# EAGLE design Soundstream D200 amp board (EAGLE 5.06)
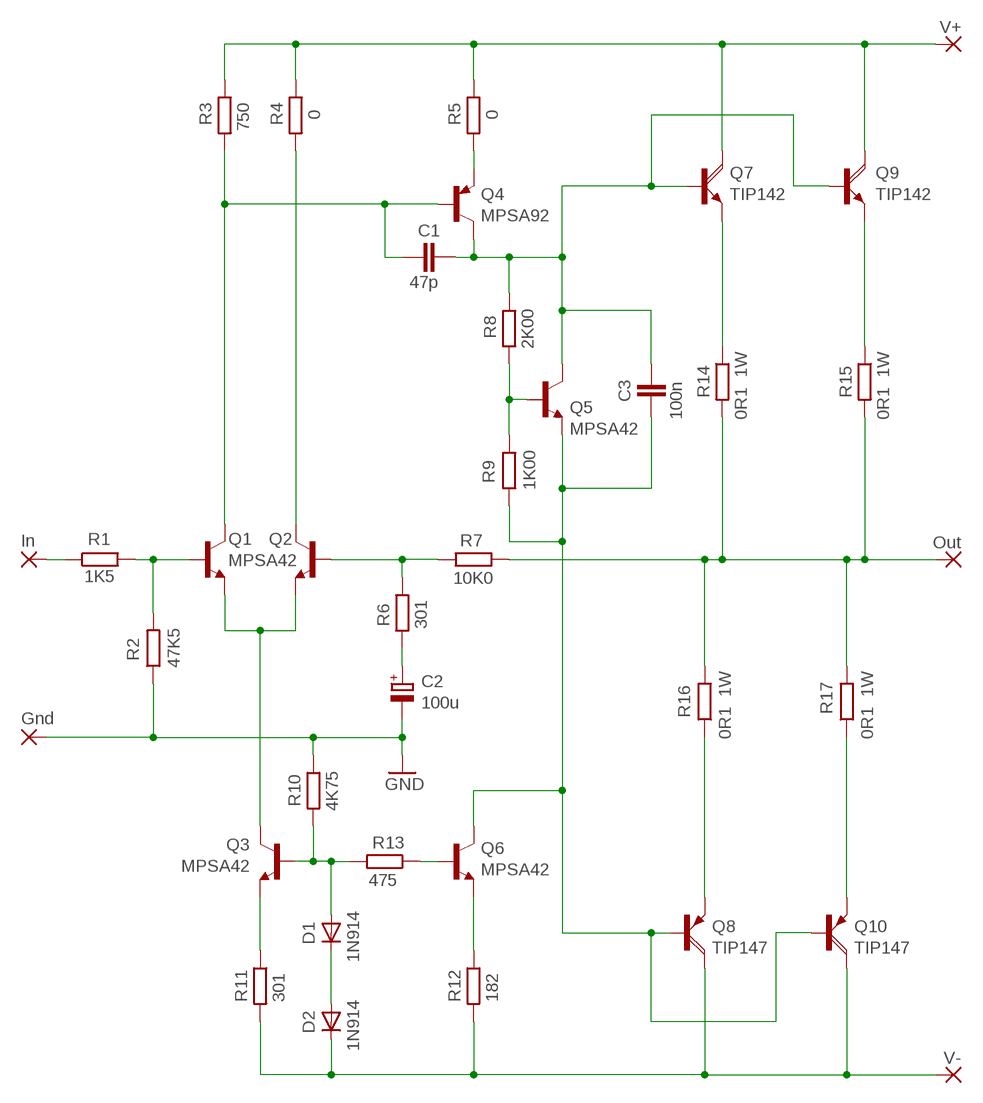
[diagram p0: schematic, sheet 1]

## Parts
C1  47p  C-EU025-025X050  [C025-025X050]
C2  100u  CPOL-EUE5-8.5  [E5-8,5]
C3  100n  C-EU025-025X050  [C025-025X050]
D1  1N914  DIODE-C1702-05  [C1702-05]
D2  1N914  DIODE-C1702-05  [C1702-05]
GND  Gnd  WIREPAD2,54/1,0  [2,54/1,0]
IN  In  WIREPAD2,54/1,0  [2,54/1,0]
OUT  Out  WIREPAD3,81/1,4  [3,81/1,4]
Q1  MPSA42  BC337-16-NPN-TO92-EBC  [TO92-EBC]
Q2  MPSA42  BC337-16-NPN-TO92-EBC  [TO92-EBC]
Q3  MPSA42  BC337-16-NPN-TO92-EBC  [TO92-EBC]
Q4  MPSA92  BC448-PNP-TO92-EBC  [TO92-EBC]
Q5  MPSA42  BC337-16-NPN-TO92-EBC  [TO92-EBC]
Q6  MPSA42  BC337-16-NPN-TO92-EBC  [TO92-EBC]
Q7  TIP142  [SOT93]
Q8  TIP147  [SOT93]
Q9  TIP142  [SOT93]
Q10  TIP147  [SOT93]
R1  1K5  R-EU_0414/5V  [0414V]
R2  47K5  R-EU_0414/5V  [0414V]
R3  750  R-EU_0414/5V  [0414V]
R4  0  R-EU_0414/5V  [0414V]
R5  0  R-EU_0414/5V  [0414V]
R6  301  R-EU_0414/5V  [0414V]
R7  10K0  R-EU_0414/5V  [0414V]
R8  2K00  R-EU_0414/5V  [0414V]
R9  1K00  R-EU_0414/5V  [0414V]
R10  4K75  R-EU_0414/5V  [0414V]
R11  301  R-EU_0414/5V  [0414V]
R12  182  R-EU_0414/5V  [0414V]
R13  475  R-EU_0414/5V  [0414V]
R14  0R1 1W  R-EU_0922V  [0922V]
R15  0R1 1W  R-EU_0922V  [0922V]
R16  0R1 1W  R-EU_0922V  [0922V]
R17  0R1 1W  R-EU_0922V  [0922V]
V+  V+  WIREPAD3,81/1,4  [3,81/1,4]
V-  V-  WIREPAD3,81/1,4  [3,81/1,4]

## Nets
GND: C2.- GND.1(P) R2.1 R10.1
N$1: Q1.E Q2.E Q3.C
N$2: Q3.E R11.1
N$3: Q6.E R12.1
N$4: C1.1 Q1.C Q4.B R3.2
N$5: D1.C D2.A
N$6: Q7.C Q9.C R3.1 R4.1 R5.1 V+.1(P)
N$7: Q10.E R17.1
N$8: D1.A Q3.B R10.2 R13.2
N$9: Q9.E R15.1
N$10: Q6.B R13.1
N$11: C3.1 Q5.E Q6.C Q8.B Q10.B R9.1
N$12: D2.C Q8.C Q10.C R11.2 R12.2 V-.1(P)
N$13: Q1.B R1.2 R2.2
N$14: Q2.B R6.1 R7.2
N$15: Q2.C R4.2
N$16: C1.2 C3.2 Q4.C Q5.C Q7.B Q9.B R8.1
N$22: Q5.B R8.2 R9.2
N$23: OUT.1(P) R7.1 R14.2 R15.2 R16.2 R17.2
N$24: C2.+ R6.2
N$28: Q7.E R14.1
N$29: IN.1(P) R1.1
N$31: Q8.E R16.1
N$40: Q4.E R5.2

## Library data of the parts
C1 C3 = rcl:C-EU: CAPACITOR, European symbol
C2 = rcl:CPOL-EU: POLARIZED CAPACITOR, European symbol
D1 D2 = diode:DIODE-: DIODE
GND IN OUT V+ V- = wirepad:WIREPAD: Wire PAD connect wire on PCB
Q1-Q3 Q5 Q6 = transistor:*-NPN-: NPN Transistror BF959 corrected 2008.03.06
Q4 = transistor:*-PNP-: PNP Transistror
Q7 Q9 = transistor-power:TIP142: NPN DARLINGTON TRANSISTOR
Q8 Q10 = transistor-power:TIP147: PNP DARLINGTON TRANSISTOR
R1-R13 = resistor:R-EU_: RESISTOR, European symbol
R14-R17 = rcl:R-EU_: RESISTOR, European symbol

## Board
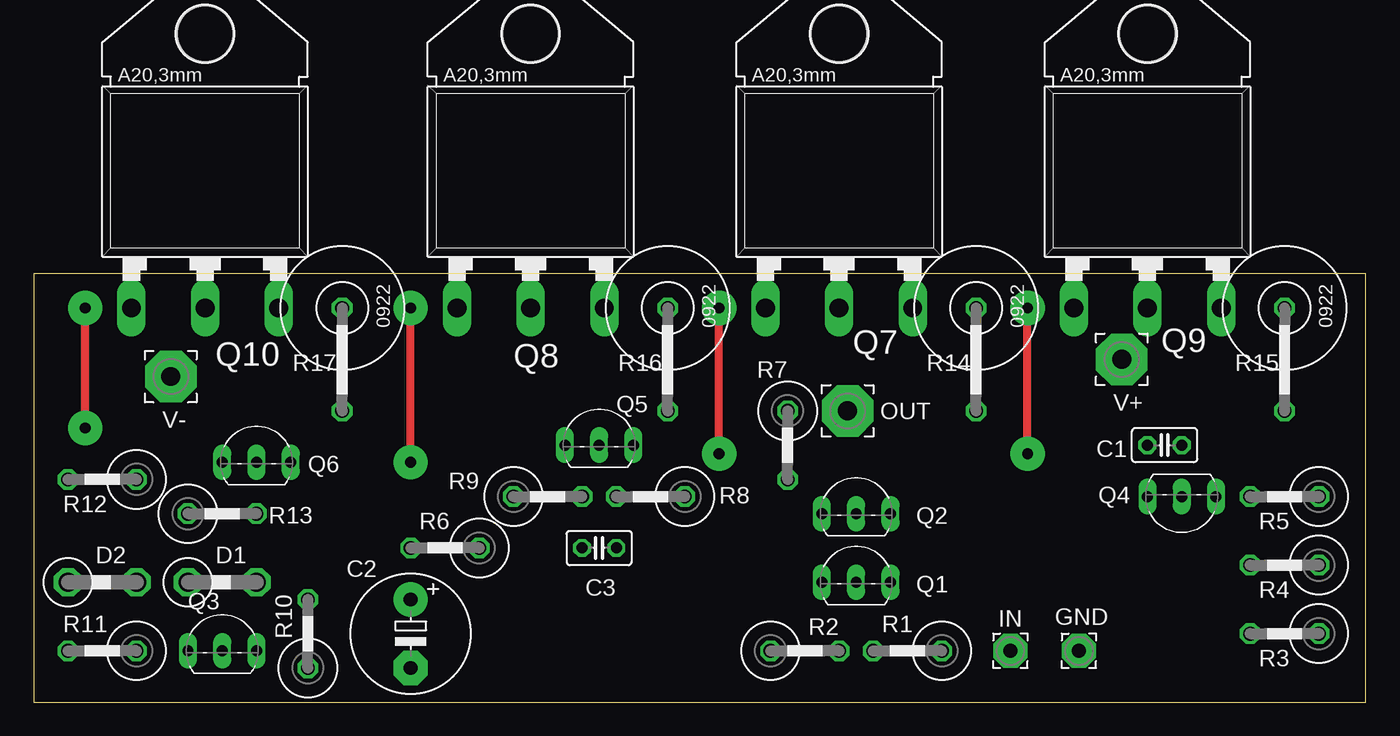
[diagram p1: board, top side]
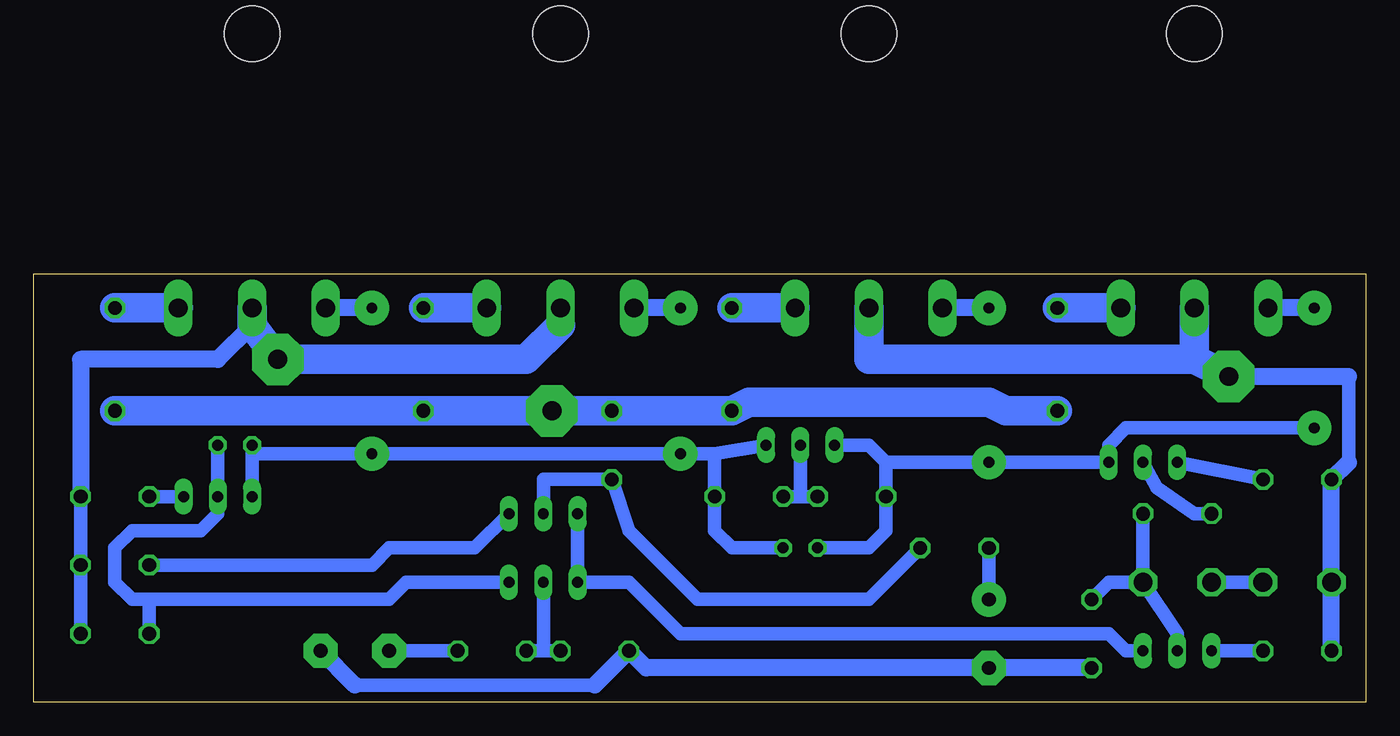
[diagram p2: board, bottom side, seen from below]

Size 98.73 x 31.74 mm. Coordinates in mm from the lower left corner, seen from the top.
Outline: 0,0 98.73,0 98.73,31.74 0,31.74 0,0
Copper layers (1*16): Top 0.035mm / dielectric 1.5mm / Bottom 0.035mm
Design rules "default": minimum track width 10mil, minimum drill 0.6mm, track to track 8mil, track to pad 8mil, pad to pad 8mil, via to via 8mil, smd to smd 8mil, copper to edge 40mil, drill to drill 8mil, minimum pad ring 10mil, minimum via ring 8mil, stop-mask expansion 4mil, vias tented up to drill 0mil, thermal gap 10mil

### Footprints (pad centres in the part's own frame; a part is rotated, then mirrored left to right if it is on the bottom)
C025-025X050 = drill 0.813 octagon: 1 -1.27,0; 2 1.27,0
E5-8,5 = drill 1.016 pad 2.54 round: + -2.54,0 | drill 1.016 pad 2.54 octagon: - 2.54,0
C1702-05 = drill 1.397 octagon: A 2.54,0; C -2.54,0
2,54/1,0 = drill 1.016 pad 2.54 octagon: 1 0,0
3,81/1,4 = drill 1.397 pad 3.81 octagon: 1 0,0
TO92-EBC = drill 0.813 long: B 0,-1.27; C 2.54,-1.27; E -2.54,-1.27
SOT93 = drill 1.397 long: B -5.461,-10.16; C 0,-10.16; E 5.461,-10.16 | hole 4.115: 0,10.16
0414V = drill 1.016 octagon: 1 -2.54,0; 2 2.54,0
0922V = drill 1.016 octagon: 1 -5.08,0; 2 2.54,0

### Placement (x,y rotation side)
C1  83.82,19.05 180 top
C2  27.94,5.08 270 top
C3  41.91,11.43 0 top
D1  13.97,8.89 0 top
D2  5.08,8.89 0 top
GND  77.47,3.81 0 top
IN  72.39,3.81 0 top
OUT  60.33,21.59 0 top
Q1  60.96,10.16 0 top
Q2  60.96,15.24 0 top
Q3  13.97,5.08 0 top
Q4  85.09,13.97 180 top
Q5  41.91,20.32 0 top
Q6  16.51,19.05 0 top
Q7  59.69,39.37 0 top
Q8  36.83,39.37 0 top
Q9  82.55,39.37 0 top
Q10  12.7,39.37 0 top
R1  64.77,3.81 180 top
R2  57.15,3.81 0 top
R3  92.71,5.08 180 top
R4  92.71,10.16 180 top
R5  92.71,15.24 180 top
R6  30.48,11.43 180 top
R7  55.88,19.05 270 top
R8  45.72,15.24 180 top
R9  38.1,15.24 0 top
R10  20.32,5.08 90 top
R11  5.08,3.81 180 top
R12  5.08,16.51 180 top
R13  13.97,13.97 0 top
R14  69.85,24.13 270 top
R15  92.71,24.13 270 top
R16  46.99,24.13 270 top
R17  22.86,24.13 270 top
V+  80.64,25.4 0 top
V-  10.16,24.13 0 top

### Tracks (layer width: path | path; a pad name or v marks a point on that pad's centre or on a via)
GND
  Bottom 1.016: 57.15,1.27 74.93,1.27
  Bottom 1.27: R10.1 C2.- 53.34,2.54 R2.1 57.15,1.27 | 74.93,1.27 GND.1
N$1
  Bottom 1.016: Q3.C 17.78,3.81 19.05,5.08 50.8,5.08 54.61,8.89 Q1.E Q2.E
N$2
  Bottom 1.016: R11.1 Q3.E
N$3
  Bottom 1.016: R12.1 Q6.E
N$4
  Bottom 1.016: 90.17,7.62 72.39,7.62 71.12,8.89 Q1.C | 90.17,7.62 91.44,7.62 92.71,8.89 92.71,11.43 91.44,12.7 86.36,12.7 85.09,13.97 Q4.B C1.1 | 90.17,7.62 R3.2
N$5
  Bottom 1.016: D2.A D1.C
N$6
  Bottom 1.016: R3.1 R4.1 R5.1 | Q7.C 59.69,27.94
  Bottom 1.27: 82.55,27.94 85.09,25.4 95.25,25.4 R5.1
  Bottom 2.184: 59.69,27.94 62.23,25.4 V+.1 82.55,27.94 Q9.C
N$7
  Bottom 2.184: Q10.E R17.1
N$8
  Bottom 1.016: Q3.B 13.97,5.08 D1.A | D1.A R13.2 | D1.A 19.05,8.89 R10.2
N$9
  Bottom 2.184: Q9.E R15.1
N$10
  Bottom 1.016: R13.1 12.7,13.97 15.49,15.88 Q6.B
N$11  (via drill 0.8 pad 2.54)
  Top 0.61: v27.94,17.78 v27.94,29.21 | v3.81,20.32 v3.81,29.21
  Bottom 1.016: Q5.E 36.83,19.05 35.56,17.78 | 35.56,17.78 R9.1 35.56,12.7 36.83,11.43 C3.1 | 35.56,17.78 v27.94,17.78 Q6.C 19.05,19.05 17.78,20.32 v3.81,20.32
  Bottom 1.27: v27.94,29.21 Q8.B | v3.81,29.21 Q10.B
N$12
  Bottom 1.016: 1.27,17.78 1.27,24.13
  Bottom 1.27: R11.2 D2.C R12.2 1.27,17.78 | 1.27,24.13 V-.1
  Bottom 2.184: Q8.C 36.83,25.4 12.7,25.4 | 12.7,25.4 Q10.C | V-.1 12.7,25.4
N$13
  Bottom 1.016: 60.96,3.81 Q1.B | 60.96,3.81 R1.2 | R2.2 60.96,3.81
N$14
  Bottom 1.016: R6.1 36.83,7.62 49.53,7.62 54.61,12.7 R7.2 60.96,16.51 Q2.B
N$15
  Bottom 1.016: Q2.C 66.04,11.43 72.39,11.43 73.66,10.16 R4.2
N$16  (via drill 0.8 pad 2.54)
  Top 0.61: v73.66,18.41 v73.66,29.21 | v50.8,18.41 v50.8,29.21
  Bottom 1.016: 48.26,18.41 Q5.C | 48.26,18.41 R8.1 48.26,12.7 46.99,11.43 C3.2 | 82.55,18.41 C1.2 | 48.26,18.41 v50.8,18.41 v73.66,18.41 82.55,18.41 | 82.55,18.41 Q4.C
  Bottom 1.27: v73.66,29.21 Q9.B | v50.8,29.21 Q7.B
N$22
  Bottom 1.016: 41.91,15.24 Q5.B | 41.91,15.24 R8.2 | R9.2 41.91,15.24
N$23
  Bottom 2.184: R17.2 26.67,21.59 27.94,22.23 45.72,22.23 R16.2 R7.1 OUT.1 R14.2 R15.2
N$24
  Bottom 1.016: C2.+ R6.2
N$28
  Bottom 2.184: Q7.E R14.1
N$29
  Bottom 1.016: R1.1 IN.1
N$31
  Bottom 2.184: Q8.E R16.1
N$40
  Bottom 1.016: Q4.E R5.2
